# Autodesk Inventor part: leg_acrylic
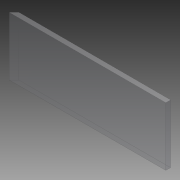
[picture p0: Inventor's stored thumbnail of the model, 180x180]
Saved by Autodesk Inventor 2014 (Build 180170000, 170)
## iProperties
Created: 2014-05
Part Number: leg_acrylic
Material: Acrylic
Document SubType Name: Modeling
Designer: t_emanb
Density: 1.188 g/cm^3
Appearance: Transparent - Clear
Author: t_emanb
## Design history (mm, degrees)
sketch "Sketch1"
  geometry: L1 (0, 0)-(101.6, 0); L2 (101.6, 0)-(101.6, 38.1); L3 (101.6, 38.1)-(0, 38.1); L4 (0, 38.1)-(0, 0)
  constraints: 8 end point, 2 parallel, 1 horizontal, 1 perpendicular
  dimensions: "d0" = 38.1 distance of L1.end L2.end; "d1" = 101.6 distance of L1.start L1.end
extrude "Extrusion1" new body sketch "Sketch1" distance "d2" = 3.0988; taper "d3" = 0 deg
sketch "Sketch2"
  geometry: L1 (101.6, 0)-(0, 0) reference; L2 (0, 0)-(0, -3.099) reference; L3 (0, -3.099)-(3.099, 0)
  constraints: 2 end point, 1 point on line
  dimensions: "d4" = 45 deg angle of L2 L3
extrude "Extrusion2" cut sketch "Sketch2" stored distance "d5" = 3.175; taper "d6" = 0 deg
body "Solid1"
